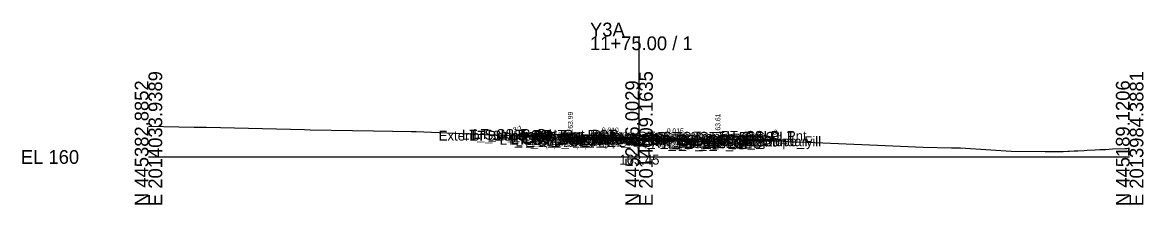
# Model space of a CAD drawing. Extents: x -26 to 205, y -10 to 5029.
# Drawn here: x -25.7 to 202.8, y 3490.3 to 3527.4 of the extents above; entities that cross this region are included whole.
import ezdxf

# ---------------------------------------------------------------- set-up
doc = ezdxf.new("R2010")
doc.units = 0
for name, color, linetype in [('Default', 7, 'Continuous'), ('Exist CMT Pavement', 7, 'Continuous'), ('Exist Cross Section Cell', 7, 'Continuous'), ('Exist XS Center Line Elevation Label', 7, 'Continuous'), ('Exist XS Ground Line', 7, 'Continuous'), ('Prop CMT Conc Surface', 7, 'Continuous'), ('Prop CMT Concrete Structures', 7, 'Continuous'), ('Prop CMT Pvmt Course 1', 7, 'Continuous'), ('Prop CMT Pvmt Course 1 CG', 7, 'Continuous'), ('Prop CMT Pvmt Course 1 Wedge', 7, 'Continuous'), ('Prop CMT Pvmt Course 2', 7, 'Continuous'), ('Prop CMT Pvmt Course 2 Wedge', 7, 'Continuous'), ('Prop CMT Pvmt Course 3', 7, 'Continuous'), ('Prop CMT Pvmt Course 3 Wedge', 7, 'Continuous'), ('Prop CMT Pvmt Surface', 7, 'Continuous'), ('Prop CMT Pvmt Wedge Surface 1', 7, 'Continuous'), ('Prop CMT Pvmt Wedge Surface 2', 7, 'Continuous'), ('Prop CMT Pvmt Wedge Surface 3', 7, 'Continuous'), ('Prop CMT Slope Grass', 7, 'Continuous'), ('Prop CMT Subgrade Earthwork', 7, 'Continuous'), ('Prop XS Earthwork Shape', 7, 'Continuous'), ('Prop XS Hydro Elevations', 7, 'Continuous'), ('Prop XS SE Text', 7, 'Continuous'), ('Prop XS Side Slope Text', 7, 'Continuous'), ('Scratch_Level_0', 7, 'Continuous')]:
    doc.layers.add(name, color=color, linetype=linetype)

msp = doc.modelspace()

# ---------------------------------------------------------------- linework, layer by layer
at = {"layer": 'Exist CMT Pavement'}
for points in [[(100, 3503.45), (97.73, 3503.46), (89.33, 3503.55), (89.02, 3503.61)], [(100, 3503.45), (112.19, 3503.25), (112.85, 3503.24)]]:
    msp.add_lwpolyline(points, dxfattribs=at)
at = {"layer": 'Exist Cross Section Cell'}
for p, q in [((100, 3500), (100, 3524.56)), ((0, 3500), (100, 3500)), ((100, 3500), (200, 3500))]:
    msp.add_line(p, q, dxfattribs=at)
at = {"layer": 'Exist XS Ground Line'}
msp.add_lwpolyline([(0, 3506.28), (9.34, 3506.07), (11.82, 3506.04), (31.83, 3505.6), (32.95, 3505.56), (45.87, 3505.31), (53.63, 3505.18), (53.96, 3505.18), (54.57, 3505.16), (68.63, 3504.59), (69.77, 3504.54), (70.65, 3504.49), (81.3, 3504.11), (82.32, 3504.1), (83.92, 3504.01), (85.28, 3503.86), (87.58, 3503.66), (87.62, 3503.86), (88.84, 3503.64), (89.33, 3503.55), (97.73, 3503.46), (100, 3503.45), (101.81, 3503.45), (112.19, 3503.25), (113.63, 3503.22), (114.94, 3503.23), (115.59, 3503.69), (117.47, 3503.64), (129.36, 3503.21), (130.39, 3503.16), (134.25, 3503.04), (150.19, 3502.35), (157.94, 3502.01), (163.68, 3501.89), (165.54, 3501.85), (171.68, 3501.44), (175.85, 3501.21), (182.81, 3501.13), (184.14, 3501.14), (186.44, 3501.11), (187.41, 3501.17), (187.73, 3501.18), (188.68, 3501.23), (189.42, 3501.27), (190.74, 3501.33), (191.31, 3501.36), (192.99, 3501.45), (193.92, 3501.5), (195.05, 3501.55), (196.5, 3501.63), (199.04, 3501.73), (199.45, 3501.75), (200, 3501.77)], dxfattribs=at)
at = {"layer": 'Prop CMT Conc Surface'}
for points in [[(86, 3503.99), (86, 3504.49), (85.5, 3504.49)], [(88, 3504.05), (86, 3503.99)], [(114.07, 3503.72), (116.07, 3503.61)], [(116.07, 3503.61), (116.07, 3504.11), (116.57, 3504.11)]]:
    msp.add_lwpolyline(points, dxfattribs=at)
at = {"layer": 'Prop CMT Concrete Structures'}
for points in [[(88, 3504.05), (86, 3503.99), (86, 3504.49), (85.5, 3504.49)], [(85.5, 3504.49), (85.5, 3503.5), (88, 3503.47)], [(88, 3503.47), (88, 3504.05)], [(114.07, 3503.72), (116.07, 3503.61), (116.07, 3504.11), (116.57, 3504.11)], [(116.57, 3504.11), (116.57, 3503.1), (114.07, 3503.14)], [(114.07, 3503.14), (114.07, 3503.72)]]:
    msp.add_lwpolyline(points, dxfattribs=at)
at = {"layer": 'Prop CMT Pvmt Course 1'}
for points in [[(100, 3503.93), (88, 3504.05)], [(88, 3504.05), (88, 3503.8)], [(88, 3503.8), (89, 3503.79)], [(89, 3503.79), (89, 3503.92)], [(89, 3503.92), (100, 3503.81)], [(100, 3503.68), (100, 3503.93)], [(100, 3503.93), (114.07, 3503.72)], [(100, 3503.68), (100, 3503.93)], [(100, 3503.81), (100, 3503.68), (100, 3503.68)], [(112.87, 3503.62), (100, 3503.81)], [(100, 3503.81), (100, 3503.68), (100, 3503.68)], [(112.87, 3503.49), (112.87, 3503.62)], [(114.07, 3503.47), (112.87, 3503.49)], [(114.07, 3503.72), (114.07, 3503.47)]]:
    msp.add_lwpolyline(points, dxfattribs=at)
at = {"layer": 'Prop CMT Pvmt Course 1 CG'}
for points in [[(88, 3503.47), (85, 3503.5), (84.67, 3503.17)], [(88, 3503.14), (88, 3503.47)], [(84.67, 3503.17), (88, 3503.14)], [(114.07, 3503.14), (117.07, 3503.09), (117.41, 3502.76)], [(114.07, 3502.81), (114.07, 3503.14)], [(117.41, 3502.76), (114.07, 3502.81)]]:
    msp.add_lwpolyline(points, dxfattribs=at)
at = {"layer": 'Prop CMT Pvmt Course 1 Wedge'}
for points in [[(100, 3503.81), (89, 3503.92)], [(100, 3503.81), (112.87, 3503.62)]]:
    msp.add_lwpolyline(points, dxfattribs=at)
at = {"layer": 'Prop CMT Pvmt Course 2'}
for points in [[(89, 3503.79), (88, 3503.8)], [(88, 3503.8), (88, 3503.47)], [(88, 3503.47), (89, 3503.46)], [(89, 3503.46), (89, 3503.79)], [(112.87, 3503.16), (112.87, 3503.49)], [(112.87, 3503.49), (114.07, 3503.47)], [(114.07, 3503.47), (114.07, 3503.14)], [(114.07, 3503.14), (112.87, 3503.16)]]:
    msp.add_lwpolyline(points, dxfattribs=at)
at = {"layer": 'Prop CMT Pvmt Course 2 Wedge'}
for points in [[(100, 3503.68), (89, 3503.79)], [(100, 3503.68), (112.87, 3503.49)]]:
    msp.add_lwpolyline(points, dxfattribs=at)
at = {"layer": 'Prop CMT Pvmt Course 3'}
for points in [[(89, 3503.46), (88, 3503.47)], [(88, 3503.47), (88, 3503.14)], [(89, 3503.13), (89, 3503.46)], [(88, 3503.14), (89, 3503.13)], [(112.87, 3503.16), (114.07, 3503.14)], [(112.87, 3502.82), (112.87, 3503.16)], [(114.07, 3502.81), (112.87, 3502.82)], [(114.07, 3503.14), (114.07, 3502.81)]]:
    msp.add_lwpolyline(points, dxfattribs=at)
at = {"layer": 'Prop CMT Pvmt Course 3 Wedge'}
for points in [[(100, 3503.35), (89, 3503.46)], [(100, 3503.35), (112.87, 3503.16)]]:
    msp.add_lwpolyline(points, dxfattribs=at)
at = {"layer": 'Prop CMT Pvmt Surface'}
for points in [[(100, 3503.93), (88, 3504.05)], [(100, 3503.93), (114.07, 3503.72)]]:
    msp.add_lwpolyline(points, dxfattribs=at)
at = {"layer": 'Prop CMT Pvmt Wedge Surface 1'}
for points in [[(88, 3503.8), (88, 3504.05)], [(89, 3503.79), (88, 3503.8)], [(100, 3503.81), (89, 3503.92)], [(89, 3503.92), (89, 3503.79)], [(100, 3503.81), (112.87, 3503.62)], [(112.87, 3503.62), (112.87, 3503.49)], [(112.87, 3503.49), (114.07, 3503.47)], [(114.07, 3503.47), (114.07, 3503.72)]]:
    msp.add_lwpolyline(points, dxfattribs=at)
at = {"layer": 'Prop CMT Pvmt Wedge Surface 2'}
for points in [[(88, 3503.8), (88, 3504.05)], [(100, 3503.68), (88, 3503.8)], [(100, 3503.68), (114.07, 3503.47)], [(114.07, 3503.47), (114.07, 3503.72)]]:
    msp.add_lwpolyline(points, dxfattribs=at)
at = {"layer": 'Prop CMT Pvmt Wedge Surface 3'}
for points in [[(88, 3503.47), (88, 3504.05)], [(100, 3503.35), (88, 3503.47)], [(114.07, 3503.14), (114.07, 3503.72)], [(100, 3503.35), (114.07, 3503.14)]]:
    msp.add_lwpolyline(points, dxfattribs=at)
at = {"layer": 'Prop CMT Slope Grass'}
for points in [[(85.5, 3504.49), (76, 3504.68), (74.95, 3504.34)], [(116.57, 3504.11), (126.07, 3504.3), (129.35, 3503.21)]]:
    msp.add_lwpolyline(points, dxfattribs=at)
at = {"layer": 'Prop CMT Subgrade Earthwork'}
for points in [[(88, 3503.14), (84.67, 3503.17), (83.3, 3504.54)], [(89, 3503.13), (89.02, 3503.61)], [(114.07, 3502.81), (117.41, 3502.76), (118.81, 3504.16)], [(89, 3503.13), (88, 3503.14)], [(112.87, 3502.82), (112.85, 3503.24)], [(112.87, 3502.82), (114.07, 3502.81)]]:
    msp.add_lwpolyline(points, dxfattribs=at)
at = {"layer": 'Prop XS Earthwork Shape'}
for points in [[(82.32, 3504.1), (83.83, 3504.01), (83.3, 3504.54), (76, 3504.68), (74.95, 3504.34), (81.3, 3504.11)], [(85.5, 3503.5), (88, 3503.47), (88, 3503.79), (88.84, 3503.64), (89.02, 3503.61), (89, 3503.13), (88, 3503.14), (84.67, 3503.17), (83.83, 3504.01), (83.92, 3504.01), (85.28, 3503.86), (85.5, 3503.84)], [(85.5, 3503.5), (88, 3503.47), (88, 3503.79), (87.62, 3503.86), (87.58, 3503.66), (85.5, 3503.84)], [(100, 3503.45), (112.19, 3503.25), (101.81, 3503.45)], [(116.57, 3503.66), (116.57, 3503.1), (114.07, 3503.14), (114.07, 3503.22), (113.63, 3503.22), (112.85, 3503.24), (112.87, 3502.82), (114.07, 3502.81), (117.41, 3502.76), (118.26, 3503.61), (117.47, 3503.64)], [(114.07, 3503.22), (114.94, 3503.23), (115.53, 3503.64), (116.07, 3503.61), (116.07, 3503.68), (116.57, 3503.66), (116.57, 3503.1), (114.07, 3503.14)], [(115.53, 3503.64), (115.59, 3503.69), (116.07, 3503.68), (116.07, 3503.61)], [(118.26, 3503.61), (129.35, 3503.21), (126.07, 3504.3), (118.81, 3504.16)]]:
    msp.add_lwpolyline(points, close=True, dxfattribs=at)

# ---------------------------------------------------------------- texts
at = {"layer": 'Default'}
msp.add_text('-', height=0.0001, dxfattribs=at).set_placement((0, 3500))
at = {"layer": 'Exist Cross Section Cell'}
for s, p in [('Y3A', (90, 3524.56)), ('11+75.00 / 1', (90, 3521.76)), ('EL 160', (-26, 3498.6))]:
    msp.add_text(s, height=2.8, dxfattribs=at).set_placement(p)
for s, p in [('E 2014033.9389', (2.8, 3490)), ('E 2014009.1635', (102.8, 3490)), ('E 2013984.3881', (202.8, 3490)), ('N 445382.8852', (0, 3490)), ('N 445286.0029', (100, 3490)), ('N 445189.1206', (200, 3490))]:
    msp.add_text(s, height=2.8, rotation=90, dxfattribs=at).set_placement(p)
at = {"layer": 'Exist XS Center Line Elevation Label'}
msp.add_text('163.45', height=2, dxfattribs=at).set_placement((95.98, 3498.45))
at = {"layer": 'Prop XS Hydro Elevations'}
for s, p in [('163.99', (86.5, 3504.99)), ('163.99', (86.5, 3504.99)), ('163.61', (116.57, 3504.61)), ('163.61', (116.57, 3504.61))]:
    msp.add_text(s, height=1, rotation=90, dxfattribs=at).set_placement(p)
at = {"layer": 'Prop XS SE Text'}
for s, rotation, p in [('0.010', 359.4271, (92.4, 3505.01)), ('0.010', 359.4271, (92.4, 3505.01)), ('0.015', 359.1436, (105.65, 3504.85)), ('0.015', 359.1436, (105.65, 3504.85))]:
    msp.add_text(s, height=1, rotation=rotation, dxfattribs=at).set_placement(p)
at = {"layer": 'Prop XS Side Slope Text'}
for rotation, p in [(18.4332, (74.5, 3504.97)), (18.4332, (74.5, 3504.97)), (341.5668, (127.22, 3504.71)), (341.5668, (127.22, 3504.71))]:
    msp.add_text('3:1', height=1, rotation=rotation, dxfattribs=at).set_placement(p)
at = {"layer": 'Scratch_Level_0'}
for s, p in [('LT_CSLP_Pnt', (66.21, 3503.68)), ('Exterior Boundary', (59.16, 3503.34)), ('LT_Sub_Trench_Out_DLT', (63.91, 3503.54)), ('LT_Slope_Fill', (65.53, 3503.34)), ('LT_CG1_Shelf_Out', (71.59, 3502.5)), ('LT_CG_Top_Face', (73.3, 3503.49)), ('LT_CG_Top_BOC', (73.82, 3503.49)), ('LT_CG_Bot_BOC', (73.85, 3502.49)), ('LT_PV_Sub_Tie_Out', (74, 3502.6)), ('LT_CG_Top_Gut', (74.27, 3502.99)), ('LT_Sub_OEOP', (74.82, 3502.17)), ('LT_PV_OEEOP_EG', (76.58, 3502.6)), ('LT_CG_Bot_IE', (77.95, 3502.47)), ('LT_Sub_OEOT', (78.12, 3502.14)), ('LT_PV2_OEOT', (78.21, 3502.8)), ('LT_PV3_OEOT', (78.21, 3502.47)), ('LT_Sub_OEEOP', (78.25, 3502.13)), ('LT_PV2_OEEOP', (78.34, 3502.79)), ('LT_PV3_OEEOP', (78.34, 3502.46)), ('LT_PV1_OEOT', (78.78, 3503.05)), ('LT_PV1_OEEOP', (78.91, 3502.92)), ('RT_PV_IEEOP_EG', (88.14, 3502.45)), ('LT_PV_IEEOP_EG', (88.19, 3502.45)), ('RT_PV2_IEEOP', (89.91, 3502.68)), ('RT_PV3_IEEOP', (89.91, 3502.35)), ('LT_PV2_IEEOP', (89.95, 3502.68)), ('LT_PV3_IEEOP', (89.95, 3502.35)), ('RT_PV1_IEEOP', (90.47, 3502.81)), ('LT_PV1_IEEOP', (90.52, 3502.81)), ('PV2_PGL', (93.91, 3502.68)), ('PV1_PGL', (94.47, 3502.93)), ('RT_PV_Sub_Tie_Out', (98.18, 3502.22)), ('RT_Sub_Trench_Out_DLT', (99.75, 3503.15)), ('RT_PV_OEEOP_EG', (100.79, 3502.22)), ('RT_Sub_OEEOP', (102.46, 3501.82)), ('RT_PV2_OEEOP', (102.56, 3502.48)), ('RT_PV3_OEEOP', (102.56, 3502.15)), ('RT_PV1_OEEOP', (103.12, 3502.61)), ('RT_CG_Top_Face', (103.71, 3503.11)), ('RT_CG1_Shelf_Out', (104, 3502.09)), ('RT_CG_Bot_IE', (104.36, 3502.13)), ('RT_Sub_OEOT', (104.53, 3501.8)), ('RT_PV2_OEOT', (104.62, 3502.47)), ('RT_PV3_OEOT', (104.62, 3502.13)), ('RT_CG_Top_Gut', (104.68, 3502.61)), ('RT_PV1_OEOT', (105.19, 3502.72)), ('RT_CG_Top_BOC', (105.23, 3503.11)), ('RT_CG_Bot_BOC', (105.26, 3502.1)), ('RT_Sub_OEOP', (107.9, 3501.75)), ('Exterior Boundary', (113.97, 3502.19)), ('RT_CSLP_Pnt', (116.62, 3503.3)), ('RT_Slope_Fill', (120.3, 3502.19))]:
    msp.add_text(s, height=2, dxfattribs=at).set_placement(p)

doc.saveas('drawing.dxf')
